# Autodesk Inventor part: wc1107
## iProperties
Shininess: 64.0
Length Units: 11272
Angle Units: 11279
Time Units: 11290
Mass Units: 11286
Length Display Precision: 3
Angle Display Precision: 2
Compacted: True
Part Number: wc1107
Document SubType Name: Modeling
Created: 2004-08
Designer: John Blackburn
Manufacturer: Standard
Standards Organization: Custom
Material: Phenolic
Density: 0.0
Volumn: 0.0
Area: 0.0
PropertySet Name: Model Information
Control State: 0
Master: False
Checked Out: False
Author: John Blackburn
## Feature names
1. Base1
